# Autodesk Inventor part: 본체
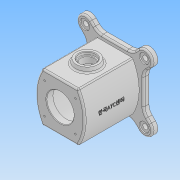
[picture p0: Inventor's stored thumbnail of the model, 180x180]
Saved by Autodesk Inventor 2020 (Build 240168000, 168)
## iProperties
Created: 2022-01
Part Number: 본체
Material: 일반
Document SubType Name: Modeling
Designer: user
Density: 1 g/cm^3
Appearance: 기본값
Mass: 457.865 g
Surface Area: 908.043 cm^2
Volume: 457.865 cm^3
Author: user
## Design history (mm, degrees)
sketch "스케치1"
  geometry: L1 (-32.942, 45)-(32.942, 45); L2 (32.942, -45)-(-32.942, -45); L3 (-45, 45)-(45, -45); L4 (45, 45)-(-45, -45); A1 r 90 centre (45, 0) between (-32.942, 45) and (-32.942, -45); A2 r 90 centre (-45, 0) between (32.942, -45) and (32.942, 45); 4 further points
  constraints: 8 end point, 6 point on circle, 3 vertical alignment, 2 centre point, 2 midpoint, 1 horizontal, 1 parallel, 1 perpendicular
  dimensions: "d0" = 90 distance of L3.end L4.end; "d1" = 90 distance of L4.start L3.end; "d3" = 90 radius of A1; "d4" = 90 radius of A2; "d5" = 45 deg angle of L1 L3; "d6" = 90 distance between parallel lines of L1 L2; "d7" = 45 distance from line of point (0, 0) L1; "d8" = 0 distance from line of L4.start L1; "d9" = 31.81981 distance from line of point (45, 0) L3; "d10" = 31.81981 distance from line of A1.centre L3; "d11" = 0 distance from line of L3.start L1; "d12" = 45 distance from line of point (-45, 0) L1; "d13" = 46.00271 distance from line of point (-45, -1.003) L1
extrude "돌출1" new body sketch "스케치1" stored distance "d14" = 110; taper "d15" = 0 deg
sketch "스케치2"
  geometry: L1 (-53, 53)-(53, 53); L2 (53, 53)-(53, -53); L3 (53, -53)-(-53, -53); L4 (-53, -53)-(-53, 53); L5 (-53, 53)-(53, -53); L6 (53, 53)-(-53, -53); L7 (0, 0)-(-54.447, 54.447); L8 (-43.841, 65.054)-(10.607, 10.607); L9 (-65.054, 43.841)-(-10.607, -10.607); L10 (-65.054, -43.841)-(-10.607, 10.607); L11 (-43.841, -65.054)-(10.607, -10.607); L12 (43.841, -65.054)-(-10.607, -10.607); L13 (65.054, -43.841)-(10.607, 10.607); L14 (65.054, 43.841)-(10.607, -10.607); L15 (43.841, 65.054)-(-10.607, 10.607); A1 r 15 centre (-54.447, 54.447) between (-43.841, 65.054) and (-65.054, 43.841); A2 r 15 centre (-54.447, -54.447) between (-65.054, -43.841) and (-43.841, -65.054); A3 r 15 centre (54.447, -54.447) between (43.841, -65.054) and (65.054, -43.841); A4 r 15 centre (54.447, 54.447) between (65.054, 43.841) and (43.841, 65.054); 8 further points
  constraints: 30 end point, 8 point on circle, 4 centre point, 3 perpendicular, 3 point on line, 2 midpoint, 2 parallel, 2 tangent, 1 coincident, 1 horizontal, 33 other
  dimensions: "d16" = 106 distance of L2.end L3.end; "d17" = 106 distance of L1.end L2.end; "d18" = 77 distance of L7.start L7.end; "d19" = 30 diameter of A1; "d22" = 360 deg dimension on L7.start A1.centre (derived)
extrude "돌출2" join sketch "스케치2" distance "d24" = 10; taper "d25" = 0 deg
sketch "스케치3"
  geometry: C1 r 25 at (0, 0); 1 further point
  constraints: 1 centre point, 1 coincident
  dimensions: "d26" = 50 diameter of C1
extrude "돌출3" cut sketch "스케치3" distance "d27" = 12; taper "d28" = 0 deg
sketch "스케치4"
  geometry: C1 r 25 at (0, 0) reference; 2 further points
  constraints: 1 coincident
hole "구멍1" sketch "스케치4" at (0, 0) diameter "d29" = 74; stored, may be unused: countersink angle "d33" = 90 deg, drill point angle "d35" = 0 deg; dims "d30" = 6, "d31" = 4, "d32" = 2, "d34" = 86
sketch "스케치5"
  geometry: C1 r 25.532 at (0, 0); 1 further point
  constraints: 1 centre point, 1 coincident
hole "구멍2" sketch "스케치5" at (0, 0) diameter "d36" = 50; stored, may be unused: countersink angle "d40" = 90 deg, drill point angle "d42" = 0 deg; dims "d37" = 6, "d38" = 4, "d39" = 2, "d41" = 12
node "작업 평면1"
sketch "스케치6"
  geometry: L1 (69.447, -55)-(69.447, -45) reference; L2 (69.447, -50)-(-69.447, -50); L3 (-69.447, -55)-(-69.447, -45) reference; L4 (0, -50)-(0, 5); C1 r 20 at (0, 5); 1 further point
  constraints: 4 end point, 3 midpoint, 1 centre point, 1 coincident, 1 vertical
  dimensions: "d44" = 55 distance of L4.start L4.end; "d45" = 40 diameter of C1
extrude "돌출4" join sketch "스케치6" stored distance "d46" = 12; taper "d47" = 15 deg
sketch "스케치7"
  geometry: C1 r 20 at (0, 0) reference; 2 further points
  constraints: 1 coincident
hole "구멍3" sketch "스케치7" at (0, 0) diameter "d48" = 30; stored, may be unused: countersink angle "d52" = 90 deg, drill point angle "d54" = 0 deg; dims "d49" = 6, "d50" = 4, "d51" = 2, "d53" = 5
sketch "스케치8"
  geometry: C1 r 15 at (0, 0) reference; 2 further points
  constraints: 1 coincident
hole "구멍4" sketch "스케치8" at (0, 0) diameter "d55" = 24; stored, may be unused: countersink angle "d59" = 90 deg, drill point angle "d61" = 0 deg; dims "d56" = 6, "d57" = 4, "d58" = 2, "d60" = 20
sketch "스케치9"
  geometry: A1 r 15 centre (-54.447, 54.447) between (-43.841, 65.054) and (-65.054, 43.841) reference; A2 r 15 centre (54.447, 54.447) between (65.054, 43.841) and (43.841, 65.054) reference; A3 r 15 centre (54.447, -54.447) between (43.841, -65.054) and (65.054, -43.841) reference; A4 r 15 centre (-54.447, -54.447) between (-65.054, -43.841) and (-43.841, -65.054) reference; 5 further points
  constraints: 4 coincident
hole "구멍5" sketch "스케치9" at (-54.447, 54.447), (54.447, 54.447), (54.447, -54.447), (-54.447, -54.447) diameter "d62" = 18; stored, may be unused: countersink angle "d66" = 90 deg, drill point angle "d68" = 0 deg; dims "d63" = 6, "d64" = 4, "d65" = 2, "d67" = 2
sketch "스케치10"
  geometry: C1 r 9 at (0, 0) reference; C2 r 9 at (0, 108.894) reference; C3 r 9 at (-108.894, 108.894) reference; C4 r 9 at (-108.894, 0) reference; 5 further points
  constraints: 4 coincident
hole "구멍6" sketch "스케치10" at (0, 0), (0, 108.894), (-108.894, 108.894), (-108.894, 0) diameter "d69" = 9; stored, may be unused: countersink angle "d73" = 90 deg, drill point angle "d75" = 0 deg; dims "d70" = 6, "d71" = 4, "d72" = 2, "d74" = 2
sketch "스케치11"
  geometry: L1 (0, 0)-(28.284, 28.284); L2 (0, 0)-(40, 0); C1 r 25 at (0, 0) reference
  constraints: 4 end point, 1 equal length, 1 horizontal
  dimensions: "d76" = 40 distance of L1.start L1.end; "d77" = 45 deg angle of L2 L1
hole "구멍7" sketch "스케치11" at (28.284, 28.284) diameter "d78" = 3.242; stored, may be unused: countersink angle "d82" = 90 deg, drill point angle "d84" = 118 deg; dims "d79" = 8, "d80" = 4, "d81" = 2, "d83" = 10
sketch "스케치12"
  geometry: L1 (0, 0)-(28.284, 28.284); L2 (0, 0)-(40, 0); C1 r 25 at (0, 0) reference
  constraints: 4 end point, 1 equal length, 1 horizontal
  dimensions: "d88" = 40 distance of L1.start L1.end; "d89" = 45 deg angle of L2 L1
hole "구멍8" sketch "스케치12" at (28.284, 28.284) diameter "d90" = 3.242; stored, may be unused: countersink angle "d94" = 90 deg, drill point angle "d96" = 118 deg; dims "d91" = 8, "d92" = 4, "d93" = 2, "d95" = 10
fillet "모깎기1" dims "d100" = 20
fillet "모깎기2" dims "d101" = 3
fillet "모깎기3" dims "d102" = 3
fillet "모깎기4" dims "d103" = 3
fillet "모깎기5" dims "d104" = 3
chamfer "모따기1" distance "d105" = 1; stored, may be unused: second distance "d106" = 2, angle "d107" = 45 deg
chamfer "모따기2" distance "d108" = 1; stored, may be unused: second distance "d109" = 2, angle "d110" = 45 deg
chamfer "모따기3" distance "d111" = 1; stored, may be unused: second distance "d112" = 2, angle "d113" = 45 deg
fillet "모깎기6" dims "d114" = 3
sketch "스케치15"
  geometry: L1 (53, -11)-(53, 21) reference; L2 (25, -54)-(-25, -54) reference; 2 further points
  constraints: 1 other
  dimensions: "d117" = 53 distance from line of L1 point (0, 6); "d118" = 60 distance from line of L2 point (0, 6)
feature "엠보싱1" sketch "스케치15" dims "d0" = 90, "d1" = 90, "d3" = 90, "d4" = 90, "d5" = 45 deg, "d6" = 90, "d7" = 45, "d8" = 0, "d9" = 31.81981, "d10" = 31.81981, "d11" = 0, "d12" = 45, "d13" = 46.00271, "d16" = 106, "d17" = 106, "d18" = 77, "d19" = 30, "d22" = 360 deg (derived), "d115" = 0.5, "d116" = 0
node "솔리드1"
pattern_circular "원형 패턴1" dims angle "d86" = 360 deg
pattern_circular "원형 패턴2" dims angle "d98" = 360 deg
feature "A9D066F2-1C7D-4E18-AEED-F7BC21143FA4" dims "d29" = 74, "d30" = 6, "d31" = 4, "d32" = 2, "d33" = 90 deg, "d34" = 86, "d35" = 0
other parameters: "d43" = 53
